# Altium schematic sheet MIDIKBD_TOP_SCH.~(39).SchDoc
size A4
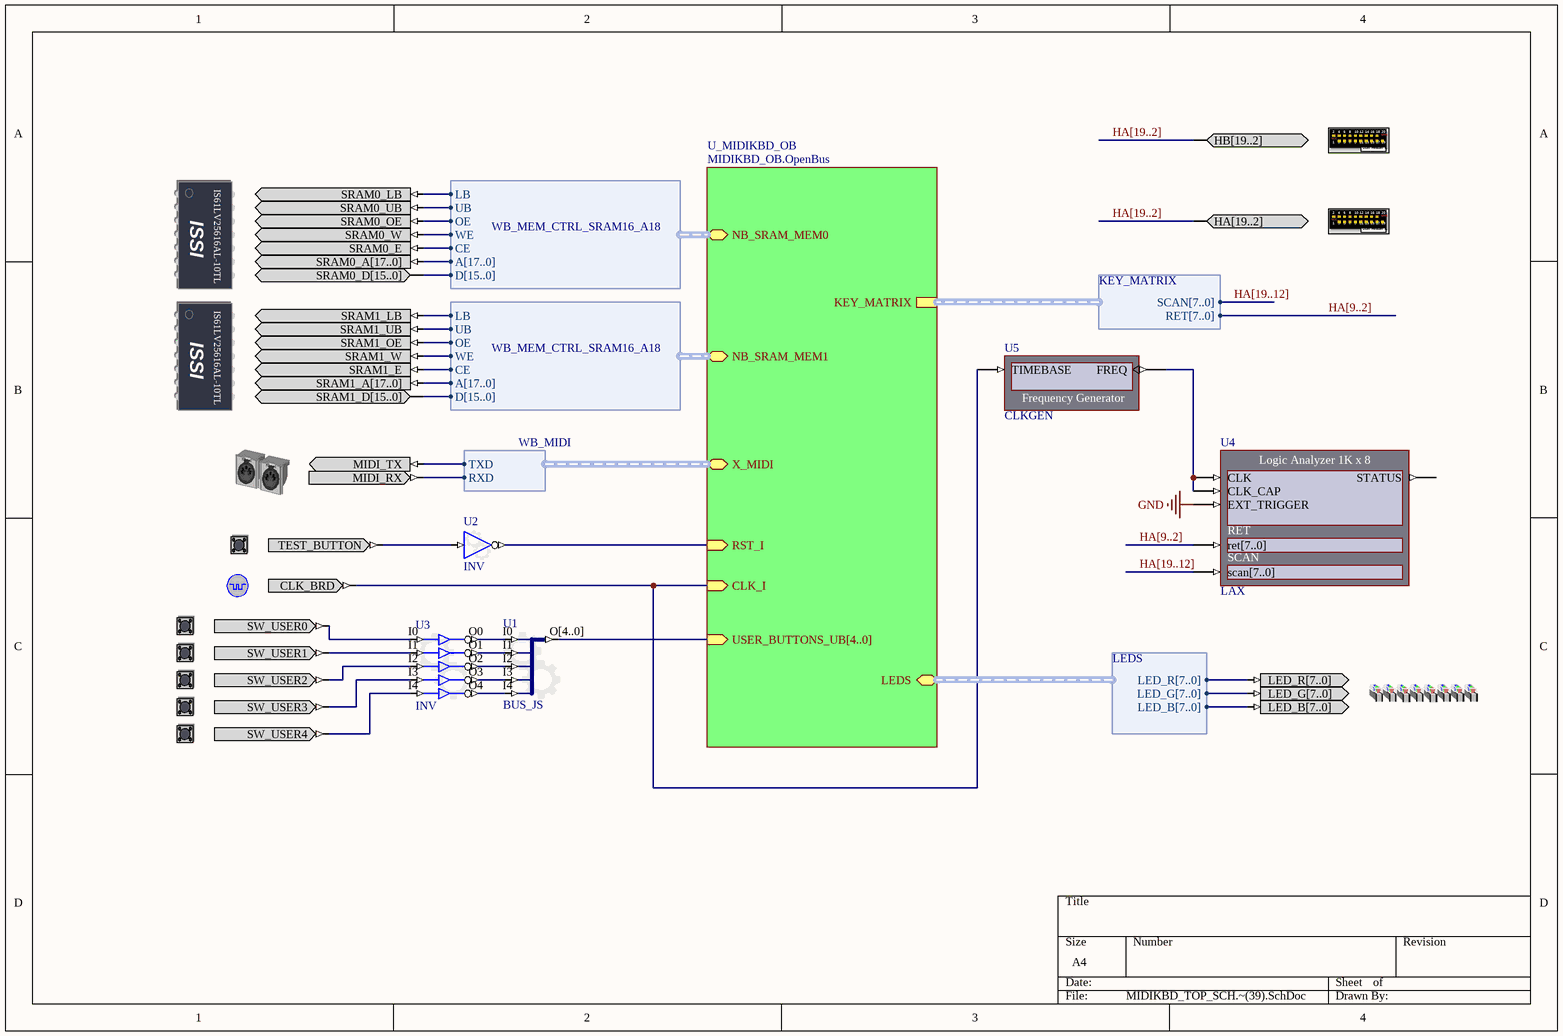
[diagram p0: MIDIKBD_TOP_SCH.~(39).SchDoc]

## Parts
(Parts that share a designator on the sheet are numbered #1, #2 ... from top to bottom, then left to right.)
?#1  USER_HEADER_B  (value not drawn)
?#2  USER_HEADER_A  (value not drawn)
?#3  SRAM0  (value not drawn)
?#4  SRAM1  (value not drawn)
?#5  MIDI  (value not drawn)
?#6  TEST_BUTTON  (value not drawn)
?#7  CLOCK_BOARD  (value not drawn)
?#8  USER_BUTTON0  (value not drawn)
?#9  USER_BUTTON1  (value not drawn)
?#10  USER_BUTTON2  (value not drawn)
?#11  LEDS_RGB  (value not drawn)
?#12  USER_BUTTON3  (value not drawn)
?#13  USER_BUTTON4  (value not drawn)
U1  BUS_JS
U2  INV
U3  INV
U4  LAX
U5  CLKGEN

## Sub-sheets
U_MIDIKBD_OB = MIDIKBD_OB.OpenBus: KEY_MATRIX (harness KEY_MATRIX), RST_I (in), CLK_I (in), LEDS (harness LEDS), X_MIDI (harness WB_MIDI), USER_BUTTONS_UB[4..0] (in), NB_SRAM_MEM0 (harness WB_MEM_CTRL_SRAM16_A18), NB_SRAM_MEM1 (harness WB_MEM_CTRL_SRAM16_A18)

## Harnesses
KEY_MATRIX: SCAN[7..0], RET[7..0]
LEDS: LED_R[7..0], LED_G[7..0], LED_B[7..0]
WB_MIDI: RXD, TXD
WB_MEM_CTRL_SRAM16_A18: D[15..0], A[17..0], CE, WE, OE, UB, LB

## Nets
GND: U4.EXT_TRIGGER
Net?#3_SRAM0_E: ?#3.SRAM0_E ; sheet U_MIDIKBD_OB/NB_SRAM_MEM0.CE
Net?#3_SRAM0_LB: ?#3.SRAM0_LB ; sheet U_MIDIKBD_OB/NB_SRAM_MEM0.LB
Net?#3_SRAM0_OE: ?#3.SRAM0_OE ; sheet U_MIDIKBD_OB/NB_SRAM_MEM0.OE
Net?#3_SRAM0_UB: ?#3.SRAM0_UB ; sheet U_MIDIKBD_OB/NB_SRAM_MEM0.UB
Net?#3_SRAM0_W: ?#3.SRAM0_W ; sheet U_MIDIKBD_OB/NB_SRAM_MEM0.WE
Net?#4_SRAM1_E: ?#4.SRAM1_E ; sheet U_MIDIKBD_OB/NB_SRAM_MEM1.CE
Net?#4_SRAM1_LB: ?#4.SRAM1_LB ; sheet U_MIDIKBD_OB/NB_SRAM_MEM1.LB
Net?#4_SRAM1_OE: ?#4.SRAM1_OE ; sheet U_MIDIKBD_OB/NB_SRAM_MEM1.OE
Net?#4_SRAM1_UB: ?#4.SRAM1_UB ; sheet U_MIDIKBD_OB/NB_SRAM_MEM1.UB
Net?#4_SRAM1_W: ?#4.SRAM1_W ; sheet U_MIDIKBD_OB/NB_SRAM_MEM1.WE
Net?#5_MIDI_RX: ?#5.MIDI_RX ; sheet U_MIDIKBD_OB/X_MIDI.RXD
Net?#5_MIDI_TX: ?#5.MIDI_TX ; sheet U_MIDIKBD_OB/X_MIDI.TXD
Net?#6_TEST_BUTTON: ?#6.TEST_BUTTON U2.I
Net?#7_CLK_BRD: ?#7.CLK_BRD U5.TIMEBASE ; sheet U_MIDIKBD_OB/CLK_I
Net?#8_SW_USER0: ?#8.SW_USER0 U3.I0
Net?#9_SW_USER1: ?#9.SW_USER1 U3.I1
Net?#10_SW_USER2: ?#10.SW_USER2 U3.I2
Net?#12_SW_USER3: ?#12.SW_USER3 U3.I3
Net?#13_SW_USER4: ?#13.SW_USER4 U3.I4
NetU1_I0: U1.I0 U3.O0
NetU1_I1: U1.I1 U3.O1
NetU1_I2: U1.I2 U3.O2
NetU1_I3: U1.I3 U3.O3
NetU1_I4: U1.I4 U3.O4
NetU2_O: U2.O ; sheet U_MIDIKBD_OB/RST_I
NetU4_CLK: U4.CLK U4.CLK_CAP U5.FREQ

Not connected (* = marked no-connect by the designer): ?#1 HB[19..2]; ?#2 HA[19..2]; ?#3 SRAM0_A[17..0] SRAM0_D[15..0]; ?#4 SRAM1_A[17..0] SRAM1_D[15..0]; ?#11 LED_B[7..0] LED_G[7..0] LED_R[7..0]; U1 O[4..0]; U4 ret[7..0] scan[7..0] STATUS

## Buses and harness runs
bus HA[9..2]
bus HA[19..2]
bus HA[19..12]

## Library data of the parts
?#1 = USER_HEADER_B: User Header B; PortComponent: True
?#2 = USER_HEADER_A: User Header A; PortComponent: True
?#3 = SRAM0: Free Static RAM - Daughterboard; PortComponent: True
?#4 = SRAM1: Free Static RAM - Daughterboard; PortComponent: True
?#5 = MIDI: MIDI Connector; PortComponent: True
?#6 = TEST_BUTTON: Test / Reset Button; PortComponent: True
?#7 = CLOCK_BOARD: Global System Clock Supply; PortComponent: True
?#8 = USER_BUTTON0: Generic User Button; PortComponent: True
?#9 = USER_BUTTON1: Generic User Button; PortComponent: True
?#10 = USER_BUTTON2: Generic User Button; PortComponent: True
?#11 = LEDS_RGB: LEDS RGB; PortComponent: True
?#12 = USER_BUTTON3: Generic User Button; PortComponent: True
?#13 = USER_BUTTON4: Generic User Button; PortComponent: True
U1 = BUS_JS: Configurable Bus Joiner/Splitter; ConfiguratorName: GENERIC_BUS_JS; ConfigurationParameters: {}Version[1.1]{}SplitterJoinerType[Joiner]{}SignalCount[5]{}SignalWidth0[1]{}GapBelow0[1000000]{}ConnectionType0[Pin]{}SignalWidth1[1]{}GapBelow1[1000000]{}ConnectionType1[Pin]{}SignalWidth2[1]{}GapBelow2[1000000]{}ConnectionType2[Pin]{}SignalWidth3[1]{}GapBelow3[1000000]{}ConnectionType3[Pin]{}SignalWidth4[1]{}GapBelow4[1000000]{}ConnectionType4[Pin]{}ShowPinNames[True]{}
U2 = INV: Configurable Inverter; ConfigurationParameters: {}Version[1.1]{}SignalCount[1]{}SignalWidth0[1]{}OutputOption0[Inverted]{}EnableMode[None]{}ShowPinNames[False]{}; ConfiguratorName: GENERIC_BUFFER
U3 = INV: Configurable Inverter; ConfigurationParameters: {}Version[1.1]{}SignalCount[5]{}SignalWidth0[1]{}OutputOption0[Inverted]{}SignalWidth1[1]{}OutputOption1[Inverted]{}SignalWidth2[1]{}OutputOption2[Inverted]{}SignalWidth3[1]{}OutputOption3[Inverted]{}SignalWidth4[1]{}OutputOption4[Inverted]{}EnableMode[None]{}ShowPinNames[True]{}; ConfiguratorName: GENERIC_BUFFER
U4 = LAX: Configurable Logic Analyzer; NEXUS_CORE: Instrument; NEXUS_JTAG_DEVICE: True; NEXUS_JTAG_ORDER: 0; ConfiguratorName: LogicAnalyser; ConfigurationParameters: {}Version[1.0]{}CaptureWidth[8]{}MemorySize[1K]{}ExtAddrWidth[10]{}Set0[RET]{}Set0_Signal0[ret(7..0)]{}Style_Set0_Signal0[Default]{}Set1[SCAN]{}Set1_Signal0[scan(7..0)]{}Style_Set1_Signal0[Default]{}ConnectSpareToGND[True]{}; ChildModel1: LAX_CFG8
U5 = CLKGEN: Frequency Generator; NEXUS_CORE: Instrument; NEXUS_JTAG_DEVICE: True; NEXUS_JTAG_ORDER: 0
